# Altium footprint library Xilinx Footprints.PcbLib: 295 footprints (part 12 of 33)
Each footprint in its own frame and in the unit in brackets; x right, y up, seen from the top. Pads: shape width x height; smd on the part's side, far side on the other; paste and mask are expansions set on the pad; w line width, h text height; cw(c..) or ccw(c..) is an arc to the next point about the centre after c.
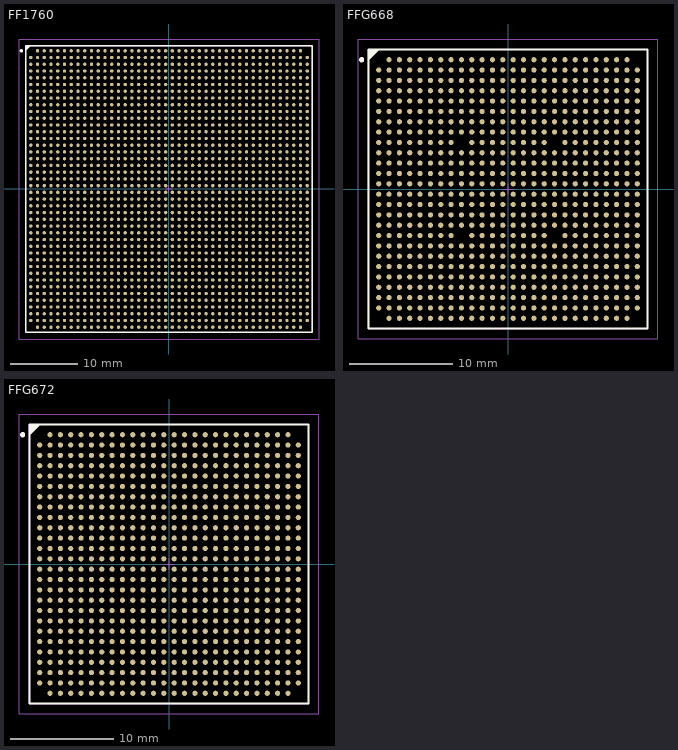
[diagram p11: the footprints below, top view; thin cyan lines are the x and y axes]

## FF1760 [mm] "1760-Ball Flip Chip Fine Pitch Ball Grid Array (FF1760)"
height 3.5
pads (1760):
  round 0.5 smd: A2(-19.5,20.5) A3(-18.5,20.5) A4(-17.5,20.5) A5(-16.5,20.5) A6(-15.5,20.5) A7(-14.5,20.5) A8(-13.5,20.5) A9(-12.5,20.5) A10(-11.5,20.5) A11(-10.5,20.5) A12(-9.5,20.5) A13(-8.5,20.5) A14(-7.5,20.5) A15(-6.5,20.5) A16(-5.5,20.5) A17(-4.5,20.5) A18(-3.5,20.5) A19(-2.5,20.5) A20(-1.5,20.5) A21(-0.5,20.5) A22(0.5,20.5) A23(1.5,20.5) A24(2.5,20.5) A25(3.5,20.5) A26(4.5,20.5) A27(5.5,20.5) A28(6.5,20.5) A29(7.5,20.5) A30(8.5,20.5) A31(9.5,20.5) A32(10.5,20.5) A33(11.5,20.5) A34(12.5,20.5) A35(13.5,20.5) A36(14.5,20.5) A37(15.5,20.5) A38(16.5,20.5) A39(17.5,20.5) A40(18.5,20.5) A41(19.5,20.5) AA1(-20.5,0.5) AA2(-19.5,0.5) AA3(-18.5,0.5) AA4(-17.5,0.5) AA5(-16.5,0.5) AA6(-15.5,0.5) AA7(-14.5,0.5) AA8(-13.5,0.5) AA9(-12.5,0.5) AA10(-11.5,0.5) AA11(-10.5,0.5) AA12(-9.5,0.5) AA13(-8.5,0.5) AA14(-7.5,0.5) AA15(-6.5,0.5) AA16(-5.5,0.5) AA17(-4.5,0.5) AA18(-3.5,0.5) AA19(-2.5,0.5) AA20(-1.5,0.5) AA21(-0.5,0.5) AA22(0.5,0.5) AA23(1.5,0.5) AA24(2.5,0.5) AA25(3.5,0.5) AA26(4.5,0.5) AA27(5.5,0.5) AA28(6.5,0.5) AA29(7.5,0.5) AA30(8.5,0.5) AA31(9.5,0.5) AA32(10.5,0.5) AA33(11.5,0.5) AA34(12.5,0.5) AA35(13.5,0.5) AA36(14.5,0.5) AA37(15.5,0.5) AA38(16.5,0.5) AA39(17.5,0.5) AA40(18.5,0.5) AA41(19.5,0.5) AA42(20.5,0.5) AB1(-20.5,-0.5) AB2(-19.5,-0.5) AB3(-18.5,-0.5) AB4(-17.5,-0.5) AB5(-16.5,-0.5) AB6(-15.5,-0.5) AB7(-14.5,-0.5) AB8(-13.5,-0.5) AB9(-12.5,-0.5) AB10(-11.5,-0.5) AB11(-10.5,-0.5) AB12(-9.5,-0.5) AB13(-8.5,-0.5) AB14(-7.5,-0.5) AB15(-6.5,-0.5) AB16(-5.5,-0.5) AB17(-4.5,-0.5) AB18(-3.5,-0.5) AB19(-2.5,-0.5) AB20(-1.5,-0.5) AB21(-0.5,-0.5) AB22(0.5,-0.5) AB23(1.5,-0.5) AB24(2.5,-0.5) AB25(3.5,-0.5) AB26(4.5,-0.5) AB27(5.5,-0.5) AB28(6.5,-0.5) AB29(7.5,-0.5) AB30(8.5,-0.5) AB31(9.5,-0.5) AB32(10.5,-0.5) AB33(11.5,-0.5) AB34(12.5,-0.5) AB35(13.5,-0.5) AB36(14.5,-0.5) AB37(15.5,-0.5) AB38(16.5,-0.5) AB39(17.5,-0.5) AB40(18.5,-0.5) AB41(19.5,-0.5) AB42(20.5,-0.5) AC1(-20.5,-1.5) AC2(-19.5,-1.5) AC3(-18.5,-1.5) AC4(-17.5,-1.5) AC5(-16.5,-1.5) AC6(-15.5,-1.5) AC7(-14.5,-1.5) AC8(-13.5,-1.5) AC9(-12.5,-1.5) AC10(-11.5,-1.5) AC11(-10.5,-1.5) AC12(-9.5,-1.5) AC13(-8.5,-1.5) AC14(-7.5,-1.5) AC15(-6.5,-1.5) AC16(-5.5,-1.5) AC17(-4.5,-1.5) AC18(-3.5,-1.5) AC19(-2.5,-1.5) AC20(-1.5,-1.5) AC21(-0.5,-1.5) AC22(0.5,-1.5) AC23(1.5,-1.5) AC24(2.5,-1.5) AC25(3.5,-1.5) AC26(4.5,-1.5) AC27(5.5,-1.5) AC28(6.5,-1.5) AC29(7.5,-1.5) AC30(8.5,-1.5) AC31(9.5,-1.5) AC32(10.5,-1.5) AC33(11.5,-1.5) AC34(12.5,-1.5) AC35(13.5,-1.5) AC36(14.5,-1.5) AC37(15.5,-1.5) AC38(16.5,-1.5) AC39(17.5,-1.5) AC40(18.5,-1.5) AC41(19.5,-1.5) AC42(20.5,-1.5) AD1(-20.5,-2.5) AD2(-19.5,-2.5) AD3(-18.5,-2.5) AD4(-17.5,-2.5) AD5(-16.5,-2.5) AD6(-15.5,-2.5) AD7(-14.5,-2.5) AD8(-13.5,-2.5) AD9(-12.5,-2.5) AD10(-11.5,-2.5) AD11(-10.5,-2.5) AD12(-9.5,-2.5) AD13(-8.5,-2.5) AD14(-7.5,-2.5) AD15(-6.5,-2.5) AD16(-5.5,-2.5) AD17(-4.5,-2.5) AD18(-3.5,-2.5) AD19(-2.5,-2.5) AD20(-1.5,-2.5) AD21(-0.5,-2.5) AD22(0.5,-2.5) AD23(1.5,-2.5) AD24(2.5,-2.5) AD25(3.5,-2.5) AD26(4.5,-2.5) AD27(5.5,-2.5) AD28(6.5,-2.5) AD29(7.5,-2.5) AD30(8.5,-2.5) AD31(9.5,-2.5) AD32(10.5,-2.5) AD33(11.5,-2.5) AD34(12.5,-2.5) AD35(13.5,-2.5) AD36(14.5,-2.5) AD37(15.5,-2.5) AD38(16.5,-2.5) AD39(17.5,-2.5) AD40(18.5,-2.5) AD41(19.5,-2.5) AD42(20.5,-2.5) AE1(-20.5,-3.5) AE2(-19.5,-3.5) AE3(-18.5,-3.5) AE4(-17.5,-3.5) AE5(-16.5,-3.5) AE6(-15.5,-3.5) AE7(-14.5,-3.5) AE8(-13.5,-3.5) AE9(-12.5,-3.5) AE10(-11.5,-3.5) AE11(-10.5,-3.5) AE12(-9.5,-3.5) AE13(-8.5,-3.5) AE14(-7.5,-3.5) AE15(-6.5,-3.5) AE16(-5.5,-3.5) AE17(-4.5,-3.5) AE18(-3.5,-3.5) AE19(-2.5,-3.5) AE20(-1.5,-3.5) AE21(-0.5,-3.5) AE22(0.5,-3.5) AE23(1.5,-3.5) AE24(2.5,-3.5) AE25(3.5,-3.5) AE26(4.5,-3.5) AE27(5.5,-3.5) AE28(6.5,-3.5) AE29(7.5,-3.5) AE30(8.5,-3.5) AE31(9.5,-3.5) AE32(10.5,-3.5) AE33(11.5,-3.5) AE34(12.5,-3.5) AE35(13.5,-3.5) AE36(14.5,-3.5) AE37(15.5,-3.5) AE38(16.5,-3.5) AE39(17.5,-3.5) AE40(18.5,-3.5) AE41(19.5,-3.5) AE42(20.5,-3.5) AF1(-20.5,-4.5) AF2(-19.5,-4.5) AF3(-18.5,-4.5) AF4(-17.5,-4.5) AF5(-16.5,-4.5) AF6(-15.5,-4.5) AF7(-14.5,-4.5) AF8(-13.5,-4.5) AF9(-12.5,-4.5) AF10(-11.5,-4.5) AF11(-10.5,-4.5) AF12(-9.5,-4.5) AF13(-8.5,-4.5) AF14(-7.5,-4.5) AF15(-6.5,-4.5) AF16(-5.5,-4.5) AF17(-4.5,-4.5) AF18(-3.5,-4.5) AF19(-2.5,-4.5) AF20(-1.5,-4.5) AF21(-0.5,-4.5) AF22(0.5,-4.5) AF23(1.5,-4.5) AF24(2.5,-4.5) AF25(3.5,-4.5) AF26(4.5,-4.5) AF27(5.5,-4.5) AF28(6.5,-4.5) AF29(7.5,-4.5) AF30(8.5,-4.5) AF31(9.5,-4.5) AF32(10.5,-4.5) AF33(11.5,-4.5) AF34(12.5,-4.5) AF35(13.5,-4.5) AF36(14.5,-4.5) AF37(15.5,-4.5) AF38(16.5,-4.5) AF39(17.5,-4.5) AF40(18.5,-4.5) AF41(19.5,-4.5) AF42(20.5,-4.5) AG1(-20.5,-5.5) AG2(-19.5,-5.5) AG3(-18.5,-5.5) AG4(-17.5,-5.5) AG5(-16.5,-5.5) AG6(-15.5,-5.5) AG7(-14.5,-5.5) AG8(-13.5,-5.5) AG9(-12.5,-5.5) AG10(-11.5,-5.5) AG11(-10.5,-5.5) AG12(-9.5,-5.5) AG13(-8.5,-5.5) AG14(-7.5,-5.5) AG15(-6.5,-5.5) AG16(-5.5,-5.5) AG17(-4.5,-5.5) AG18(-3.5,-5.5) AG19(-2.5,-5.5) AG20(-1.5,-5.5) AG21(-0.5,-5.5) AG22(0.5,-5.5) AG23(1.5,-5.5) AG24(2.5,-5.5) AG25(3.5,-5.5) AG26(4.5,-5.5) AG27(5.5,-5.5) AG28(6.5,-5.5) AG29(7.5,-5.5) AG30(8.5,-5.5) AG31(9.5,-5.5) AG32(10.5,-5.5) AG33(11.5,-5.5) AG34(12.5,-5.5) AG35(13.5,-5.5) AG36(14.5,-5.5) AG37(15.5,-5.5) AG38(16.5,-5.5) AG39(17.5,-5.5) AG40(18.5,-5.5) AG41(19.5,-5.5) AG42(20.5,-5.5) AH1(-20.5,-6.5) AH2(-19.5,-6.5) AH3(-18.5,-6.5) AH4(-17.5,-6.5) AH5(-16.5,-6.5) AH6(-15.5,-6.5) AH7(-14.5,-6.5) AH8(-13.5,-6.5) AH9(-12.5,-6.5) AH10(-11.5,-6.5) AH11(-10.5,-6.5) AH12(-9.5,-6.5) AH13(-8.5,-6.5) AH14(-7.5,-6.5) AH15(-6.5,-6.5) AH16(-5.5,-6.5) AH17(-4.5,-6.5) AH18(-3.5,-6.5) AH19(-2.5,-6.5) AH20(-1.5,-6.5) AH21(-0.5,-6.5) AH22(0.5,-6.5) AH23(1.5,-6.5) AH24(2.5,-6.5) AH25(3.5,-6.5) AH26(4.5,-6.5) AH27(5.5,-6.5) AH28(6.5,-6.5) AH29(7.5,-6.5) AH30(8.5,-6.5) AH31(9.5,-6.5) AH32(10.5,-6.5) AH33(11.5,-6.5) AH34(12.5,-6.5) AH35(13.5,-6.5) AH36(14.5,-6.5) AH37(15.5,-6.5) AH38(16.5,-6.5) AH39(17.5,-6.5) AH40(18.5,-6.5) AH41(19.5,-6.5) AH42(20.5,-6.5) AJ1(-20.5,-7.5) AJ2(-19.5,-7.5) AJ3(-18.5,-7.5) AJ4(-17.5,-7.5) AJ5(-16.5,-7.5) AJ6(-15.5,-7.5) AJ7(-14.5,-7.5) AJ8(-13.5,-7.5) AJ9(-12.5,-7.5) AJ10(-11.5,-7.5) AJ11(-10.5,-7.5) AJ12(-9.5,-7.5) AJ13(-8.5,-7.5) AJ14(-7.5,-7.5) AJ15(-6.5,-7.5) AJ16(-5.5,-7.5) AJ17(-4.5,-7.5) AJ18(-3.5,-7.5) AJ19(-2.5,-7.5) AJ20(-1.5,-7.5) AJ21(-0.5,-7.5) AJ22(0.5,-7.5) AJ23(1.5,-7.5) AJ24(2.5,-7.5) AJ25(3.5,-7.5) AJ26(4.5,-7.5) AJ27(5.5,-7.5) AJ28(6.5,-7.5) AJ29(7.5,-7.5) AJ30(8.5,-7.5) AJ31(9.5,-7.5) AJ32(10.5,-7.5) AJ33(11.5,-7.5) AJ34(12.5,-7.5) AJ35(13.5,-7.5) AJ36(14.5,-7.5) AJ37(15.5,-7.5) AJ38(16.5,-7.5) AJ39(17.5,-7.5) AJ40(18.5,-7.5) AJ41(19.5,-7.5) AJ42(20.5,-7.5) AK1(-20.5,-8.5) AK2(-19.5,-8.5) AK3(-18.5,-8.5) AK4(-17.5,-8.5) AK5(-16.5,-8.5) AK6(-15.5,-8.5) AK7(-14.5,-8.5) AK8(-13.5,-8.5) AK9(-12.5,-8.5) AK10(-11.5,-8.5) AK11(-10.5,-8.5) AK12(-9.5,-8.5) AK13(-8.5,-8.5) AK14(-7.5,-8.5) AK15(-6.5,-8.5) AK16(-5.5,-8.5) AK17(-4.5,-8.5) AK18(-3.5,-8.5) AK19(-2.5,-8.5) AK20(-1.5,-8.5) AK21(-0.5,-8.5) AK22(0.5,-8.5) AK23(1.5,-8.5) AK24(2.5,-8.5) AK25(3.5,-8.5) AK26(4.5,-8.5) AK27(5.5,-8.5) AK28(6.5,-8.5) AK29(7.5,-8.5) AK30(8.5,-8.5) AK31(9.5,-8.5) AK32(10.5,-8.5) AK33(11.5,-8.5) AK34(12.5,-8.5) AK35(13.5,-8.5) AK36(14.5,-8.5) AK37(15.5,-8.5) AK38(16.5,-8.5) AK39(17.5,-8.5) AK40(18.5,-8.5) AK41(19.5,-8.5) AK42(20.5,-8.5) AL1(-20.5,-9.5) AL2(-19.5,-9.5) AL3(-18.5,-9.5) AL4(-17.5,-9.5) AL5(-16.5,-9.5) AL6(-15.5,-9.5) AL7(-14.5,-9.5) AL8(-13.5,-9.5) AL9(-12.5,-9.5) AL10(-11.5,-9.5) AL11(-10.5,-9.5) AL12(-9.5,-9.5) AL13(-8.5,-9.5) AL14(-7.5,-9.5) AL15(-6.5,-9.5) AL16(-5.5,-9.5) AL17(-4.5,-9.5) AL18(-3.5,-9.5) AL19(-2.5,-9.5) AL20(-1.5,-9.5) AL21(-0.5,-9.5) AL22(0.5,-9.5) AL23(1.5,-9.5) AL24(2.5,-9.5) AL25(3.5,-9.5) AL26(4.5,-9.5) AL27(5.5,-9.5) AL28(6.5,-9.5) AL29(7.5,-9.5) AL30(8.5,-9.5) AL31(9.5,-9.5) AL32(10.5,-9.5) AL33(11.5,-9.5) AL34(12.5,-9.5) AL35(13.5,-9.5) AL36(14.5,-9.5) AL37(15.5,-9.5) AL38(16.5,-9.5) AL39(17.5,-9.5) AL40(18.5,-9.5) AL41(19.5,-9.5) AL42(20.5,-9.5) AM1(-20.5,-10.5) AM2(-19.5,-10.5) AM3(-18.5,-10.5) AM4(-17.5,-10.5) AM5(-16.5,-10.5) AM6(-15.5,-10.5) AM7(-14.5,-10.5) AM8(-13.5,-10.5) AM9(-12.5,-10.5) AM10(-11.5,-10.5) AM11(-10.5,-10.5) AM12(-9.5,-10.5) AM13(-8.5,-10.5) AM14(-7.5,-10.5) AM15(-6.5,-10.5) AM16(-5.5,-10.5) AM17(-4.5,-10.5) AM18(-3.5,-10.5) AM19(-2.5,-10.5) AM20(-1.5,-10.5) AM21(-0.5,-10.5) AM22(0.5,-10.5) AM23(1.5,-10.5) AM24(2.5,-10.5) AM25(3.5,-10.5) AM26(4.5,-10.5) AM27(5.5,-10.5) AM28(6.5,-10.5) AM29(7.5,-10.5) AM30(8.5,-10.5) AM31(9.5,-10.5) AM32(10.5,-10.5) AM33(11.5,-10.5) AM34(12.5,-10.5) AM35(13.5,-10.5) AM36(14.5,-10.5) AM37(15.5,-10.5) AM38(16.5,-10.5) AM39(17.5,-10.5) AM40(18.5,-10.5) AM41(19.5,-10.5) AM42(20.5,-10.5) AN1(-20.5,-11.5) AN2(-19.5,-11.5) AN3(-18.5,-11.5) AN4(-17.5,-11.5) AN5(-16.5,-11.5) AN6(-15.5,-11.5) AN7(-14.5,-11.5) AN8(-13.5,-11.5) AN9(-12.5,-11.5) AN10(-11.5,-11.5) AN11(-10.5,-11.5) AN12(-9.5,-11.5) AN13(-8.5,-11.5) AN14(-7.5,-11.5) AN15(-6.5,-11.5) AN16(-5.5,-11.5) AN17(-4.5,-11.5) AN18(-3.5,-11.5) AN19(-2.5,-11.5) AN20(-1.5,-11.5) AN21(-0.5,-11.5) AN22(0.5,-11.5) AN23(1.5,-11.5) AN24(2.5,-11.5) AN25(3.5,-11.5) AN26(4.5,-11.5) AN27(5.5,-11.5) AN28(6.5,-11.5) AN29(7.5,-11.5) AN30(8.5,-11.5) AN31(9.5,-11.5) AN32(10.5,-11.5) AN33(11.5,-11.5) AN34(12.5,-11.5) AN35(13.5,-11.5) AN36(14.5,-11.5) AN37(15.5,-11.5) AN38(16.5,-11.5) AN39(17.5,-11.5) AN40(18.5,-11.5) AN41(19.5,-11.5) AN42(20.5,-11.5) AP1(-20.5,-12.5) AP2(-19.5,-12.5) AP3(-18.5,-12.5) AP4(-17.5,-12.5) AP5(-16.5,-12.5) AP6(-15.5,-12.5) AP7(-14.5,-12.5) AP8(-13.5,-12.5) AP9(-12.5,-12.5) AP10(-11.5,-12.5) AP11(-10.5,-12.5) AP12(-9.5,-12.5) AP13(-8.5,-12.5) AP14(-7.5,-12.5) AP15(-6.5,-12.5) AP16(-5.5,-12.5) AP17(-4.5,-12.5) AP18(-3.5,-12.5) AP19(-2.5,-12.5) AP20(-1.5,-12.5) AP21(-0.5,-12.5) AP22(0.5,-12.5) AP23(1.5,-12.5) AP24(2.5,-12.5) AP25(3.5,-12.5) AP26(4.5,-12.5) AP27(5.5,-12.5) AP28(6.5,-12.5) AP29(7.5,-12.5) AP30(8.5,-12.5) AP31(9.5,-12.5) AP32(10.5,-12.5) AP33(11.5,-12.5) AP34(12.5,-12.5) AP35(13.5,-12.5) AP36(14.5,-12.5) AP37(15.5,-12.5) AP38(16.5,-12.5) AP39(17.5,-12.5) AP40(18.5,-12.5) AP41(19.5,-12.5) AP42(20.5,-12.5) AR1(-20.5,-13.5) AR2(-19.5,-13.5) AR3(-18.5,-13.5) AR4(-17.5,-13.5) AR5(-16.5,-13.5) AR6(-15.5,-13.5) AR7(-14.5,-13.5) AR8(-13.5,-13.5) AR9(-12.5,-13.5) AR10(-11.5,-13.5) AR11(-10.5,-13.5) AR12(-9.5,-13.5) AR13(-8.5,-13.5) AR14(-7.5,-13.5) AR15(-6.5,-13.5) AR16(-5.5,-13.5) AR17(-4.5,-13.5) AR18(-3.5,-13.5) AR19(-2.5,-13.5) AR20(-1.5,-13.5) AR21(-0.5,-13.5) AR22(0.5,-13.5) AR23(1.5,-13.5) AR24(2.5,-13.5) AR25(3.5,-13.5) AR26(4.5,-13.5) AR27(5.5,-13.5) AR28(6.5,-13.5) AR29(7.5,-13.5) AR30(8.5,-13.5) AR31(9.5,-13.5) AR32(10.5,-13.5) AR33(11.5,-13.5) AR34(12.5,-13.5) AR35(13.5,-13.5) AR36(14.5,-13.5) AR37(15.5,-13.5) AR38(16.5,-13.5) AR39(17.5,-13.5) AR40(18.5,-13.5) AR41(19.5,-13.5) AR42(20.5,-13.5) AT1(-20.5,-14.5) AT2(-19.5,-14.5) AT3(-18.5,-14.5) AT4(-17.5,-14.5) AT5(-16.5,-14.5) AT6(-15.5,-14.5) AT7(-14.5,-14.5) AT8(-13.5,-14.5) AT9(-12.5,-14.5) AT10(-11.5,-14.5) AT11(-10.5,-14.5) AT12(-9.5,-14.5) AT13(-8.5,-14.5) AT14(-7.5,-14.5) AT15(-6.5,-14.5) AT16(-5.5,-14.5) AT17(-4.5,-14.5) AT18(-3.5,-14.5) AT19(-2.5,-14.5) AT20(-1.5,-14.5) AT21(-0.5,-14.5) AT22(0.5,-14.5) AT23(1.5,-14.5) AT24(2.5,-14.5) AT25(3.5,-14.5) AT26(4.5,-14.5) AT27(5.5,-14.5) AT28(6.5,-14.5) AT29(7.5,-14.5) AT30(8.5,-14.5) AT31(9.5,-14.5) AT32(10.5,-14.5) AT33(11.5,-14.5) AT34(12.5,-14.5) AT35(13.5,-14.5) AT36(14.5,-14.5) AT37(15.5,-14.5) AT38(16.5,-14.5) AT39(17.5,-14.5) AT40(18.5,-14.5) AT41(19.5,-14.5) AT42(20.5,-14.5) AU1(-20.5,-15.5) AU2(-19.5,-15.5) AU3(-18.5,-15.5) AU4(-17.5,-15.5) AU5(-16.5,-15.5) AU6(-15.5,-15.5) AU7(-14.5,-15.5) AU8(-13.5,-15.5) AU9(-12.5,-15.5) AU10(-11.5,-15.5) AU11(-10.5,-15.5) AU12(-9.5,-15.5) AU13(-8.5,-15.5) AU14(-7.5,-15.5) AU15(-6.5,-15.5) AU16(-5.5,-15.5) AU17(-4.5,-15.5) AU18(-3.5,-15.5) AU19(-2.5,-15.5) AU20(-1.5,-15.5) AU21(-0.5,-15.5) AU22(0.5,-15.5) AU23(1.5,-15.5) AU24(2.5,-15.5) AU25(3.5,-15.5) AU26(4.5,-15.5) AU27(5.5,-15.5) AU28(6.5,-15.5) AU29(7.5,-15.5) AU30(8.5,-15.5) AU31(9.5,-15.5) AU32(10.5,-15.5) AU33(11.5,-15.5) AU34(12.5,-15.5) AU35(13.5,-15.5) AU36(14.5,-15.5) AU37(15.5,-15.5) AU38(16.5,-15.5) AU39(17.5,-15.5) AU40(18.5,-15.5) AU41(19.5,-15.5) AU42(20.5,-15.5) AV1(-20.5,-16.5) AV2(-19.5,-16.5) AV3(-18.5,-16.5) AV4(-17.5,-16.5) AV5(-16.5,-16.5) AV6(-15.5,-16.5) AV7(-14.5,-16.5) AV8(-13.5,-16.5) AV9(-12.5,-16.5) AV10(-11.5,-16.5) AV11(-10.5,-16.5) AV12(-9.5,-16.5) AV13(-8.5,-16.5) AV14(-7.5,-16.5) AV15(-6.5,-16.5) AV16(-5.5,-16.5) AV17(-4.5,-16.5) AV18(-3.5,-16.5) AV19(-2.5,-16.5) AV20(-1.5,-16.5) AV21(-0.5,-16.5) AV22(0.5,-16.5) AV23(1.5,-16.5) AV24(2.5,-16.5) AV25(3.5,-16.5) AV26(4.5,-16.5) AV27(5.5,-16.5) AV28(6.5,-16.5) AV29(7.5,-16.5) AV30(8.5,-16.5) AV31(9.5,-16.5) AV32(10.5,-16.5) AV33(11.5,-16.5) AV34(12.5,-16.5) AV35(13.5,-16.5) AV36(14.5,-16.5) AV37(15.5,-16.5) AV38(16.5,-16.5) AV39(17.5,-16.5) AV40(18.5,-16.5) AV41(19.5,-16.5) AV42(20.5,-16.5) AW1(-20.5,-17.5) AW2(-19.5,-17.5) AW3(-18.5,-17.5) AW4(-17.5,-17.5) AW5(-16.5,-17.5) AW6(-15.5,-17.5) AW7(-14.5,-17.5) AW8(-13.5,-17.5) AW9(-12.5,-17.5) AW10(-11.5,-17.5) AW11(-10.5,-17.5) AW12(-9.5,-17.5) AW13(-8.5,-17.5) AW14(-7.5,-17.5) AW15(-6.5,-17.5) AW16(-5.5,-17.5) AW17(-4.5,-17.5) AW18(-3.5,-17.5) AW19(-2.5,-17.5) AW20(-1.5,-17.5) AW21(-0.5,-17.5) AW22(0.5,-17.5) AW23(1.5,-17.5) AW24(2.5,-17.5) AW25(3.5,-17.5) AW26(4.5,-17.5) AW27(5.5,-17.5) AW28(6.5,-17.5) AW29(7.5,-17.5) AW30(8.5,-17.5) AW31(9.5,-17.5) AW32(10.5,-17.5) AW33(11.5,-17.5) AW34(12.5,-17.5) AW35(13.5,-17.5) AW36(14.5,-17.5) AW37(15.5,-17.5) AW38(16.5,-17.5) AW39(17.5,-17.5) AW40(18.5,-17.5) AW41(19.5,-17.5) AW42(20.5,-17.5) AY1(-20.5,-18.5) AY2(-19.5,-18.5) AY3(-18.5,-18.5) AY4(-17.5,-18.5) AY5(-16.5,-18.5) AY6(-15.5,-18.5) AY7(-14.5,-18.5) AY8(-13.5,-18.5) AY9(-12.5,-18.5) AY10(-11.5,-18.5) AY11(-10.5,-18.5) AY12(-9.5,-18.5) AY13(-8.5,-18.5) AY14(-7.5,-18.5) AY15(-6.5,-18.5) AY16(-5.5,-18.5) AY17(-4.5,-18.5) AY18(-3.5,-18.5) AY19(-2.5,-18.5) AY20(-1.5,-18.5) AY21(-0.5,-18.5) AY22(0.5,-18.5) AY23(1.5,-18.5) AY24(2.5,-18.5) AY25(3.5,-18.5) AY26(4.5,-18.5) AY27(5.5,-18.5) AY28(6.5,-18.5) AY29(7.5,-18.5) AY30(8.5,-18.5) AY31(9.5,-18.5) AY32(10.5,-18.5) AY33(11.5,-18.5) AY34(12.5,-18.5) AY35(13.5,-18.5) AY36(14.5,-18.5) AY37(15.5,-18.5) AY38(16.5,-18.5) AY39(17.5,-18.5) AY40(18.5,-18.5) AY41(19.5,-18.5) AY42(20.5,-18.5) B1(-20.5,19.5) B2(-19.5,19.5) B3(-18.5,19.5) B4(-17.5,19.5) B5(-16.5,19.5) B6(-15.5,19.5) B7(-14.5,19.5) B8(-13.5,19.5) B9(-12.5,19.5) B10(-11.5,19.5) B11(-10.5,19.5) B12(-9.5,19.5) B13(-8.5,19.5) B14(-7.5,19.5) B15(-6.5,19.5) B16(-5.5,19.5) B17(-4.5,19.5) B18(-3.5,19.5) B19(-2.5,19.5) B20(-1.5,19.5) B21(-0.5,19.5) B22(0.5,19.5) B23(1.5,19.5) B24(2.5,19.5) B25(3.5,19.5) B26(4.5,19.5) B27(5.5,19.5) B28(6.5,19.5) B29(7.5,19.5) B30(8.5,19.5) B31(9.5,19.5) B32(10.5,19.5) B33(11.5,19.5) B34(12.5,19.5) B35(13.5,19.5) B36(14.5,19.5) B37(15.5,19.5) B38(16.5,19.5) B39(17.5,19.5) B40(18.5,19.5) B41(19.5,19.5) B42(20.5,19.5) BA1(-20.5,-19.5) BA2(-19.5,-19.5) BA3(-18.5,-19.5) BA4(-17.5,-19.5) BA5(-16.5,-19.5) BA6(-15.5,-19.5) BA7(-14.5,-19.5) BA8(-13.5,-19.5) BA9(-12.5,-19.5) BA10(-11.5,-19.5) BA11(-10.5,-19.5) BA12(-9.5,-19.5) BA13(-8.5,-19.5) BA14(-7.5,-19.5) BA15(-6.5,-19.5) BA16(-5.5,-19.5) BA17(-4.5,-19.5) BA18(-3.5,-19.5) BA19(-2.5,-19.5) BA20(-1.5,-19.5) BA21(-0.5,-19.5) BA22(0.5,-19.5) BA23(1.5,-19.5) BA24(2.5,-19.5) BA25(3.5,-19.5) BA26(4.5,-19.5) BA27(5.5,-19.5) BA28(6.5,-19.5) BA29(7.5,-19.5) BA30(8.5,-19.5) BA31(9.5,-19.5) BA32(10.5,-19.5) BA33(11.5,-19.5) BA34(12.5,-19.5) BA35(13.5,-19.5) BA36(14.5,-19.5) BA37(15.5,-19.5) BA38(16.5,-19.5) BA39(17.5,-19.5) BA40(18.5,-19.5) BA41(19.5,-19.5) BA42(20.5,-19.5) BB2(-19.5,-20.5) BB3(-18.5,-20.5) BB4(-17.5,-20.5) BB5(-16.5,-20.5) BB6(-15.5,-20.5) BB7(-14.5,-20.5) BB8(-13.5,-20.5) BB9(-12.5,-20.5) BB10(-11.5,-20.5) BB11(-10.5,-20.5) BB12(-9.5,-20.5) BB13(-8.5,-20.5) BB14(-7.5,-20.5) BB15(-6.5,-20.5) BB16(-5.5,-20.5) BB17(-4.5,-20.5) BB18(-3.5,-20.5) BB19(-2.5,-20.5) BB20(-1.5,-20.5) BB21(-0.5,-20.5) BB22(0.5,-20.5) BB23(1.5,-20.5) BB24(2.5,-20.5) BB25(3.5,-20.5) BB26(4.5,-20.5) BB27(5.5,-20.5) BB28(6.5,-20.5) BB29(7.5,-20.5) BB30(8.5,-20.5) BB31(9.5,-20.5) BB32(10.5,-20.5) BB33(11.5,-20.5) BB34(12.5,-20.5) BB35(13.5,-20.5) BB36(14.5,-20.5) BB37(15.5,-20.5) BB38(16.5,-20.5) BB39(17.5,-20.5) BB40(18.5,-20.5) BB41(19.5,-20.5) C1(-20.5,18.5) C2(-19.5,18.5) C3(-18.5,18.5) C4(-17.5,18.5) C5(-16.5,18.5) C6(-15.5,18.5) C7(-14.5,18.5) C8(-13.5,18.5) C9(-12.5,18.5) C10(-11.5,18.5) C11(-10.5,18.5) C12(-9.5,18.5) C13(-8.5,18.5) C14(-7.5,18.5) C15(-6.5,18.5) C16(-5.5,18.5) C17(-4.5,18.5) C18(-3.5,18.5) C19(-2.5,18.5) C20(-1.5,18.5) C21(-0.5,18.5) C22(0.5,18.5) C23(1.5,18.5) C24(2.5,18.5) C25(3.5,18.5) C26(4.5,18.5) C27(5.5,18.5) C28(6.5,18.5) C29(7.5,18.5) C30(8.5,18.5) C31(9.5,18.5) C32(10.5,18.5) C33(11.5,18.5) C34(12.5,18.5) C35(13.5,18.5) C36(14.5,18.5) C37(15.5,18.5) C38(16.5,18.5) C39(17.5,18.5) C40(18.5,18.5) C41(19.5,18.5) C42(20.5,18.5) D1(-20.5,17.5) D2(-19.5,17.5) D3(-18.5,17.5) D4(-17.5,17.5) D5(-16.5,17.5) D6(-15.5,17.5) D7(-14.5,17.5) D8(-13.5,17.5) D9(-12.5,17.5) D10(-11.5,17.5) D11(-10.5,17.5) D12(-9.5,17.5) D13(-8.5,17.5) D14(-7.5,17.5) D15(-6.5,17.5) D16(-5.5,17.5) D17(-4.5,17.5) D18(-3.5,17.5) D19(-2.5,17.5) D20(-1.5,17.5) D21(-0.5,17.5) D22(0.5,17.5) D23(1.5,17.5) D24(2.5,17.5) D25(3.5,17.5) D26(4.5,17.5) D27(5.5,17.5) D28(6.5,17.5) D29(7.5,17.5) D30(8.5,17.5) D31(9.5,17.5) D32(10.5,17.5) D33(11.5,17.5) D34(12.5,17.5) D35(13.5,17.5) D36(14.5,17.5) D37(15.5,17.5) D38(16.5,17.5) D39(17.5,17.5) D40(18.5,17.5) D41(19.5,17.5) D42(20.5,17.5) E1(-20.5,16.5) E2(-19.5,16.5) E3(-18.5,16.5) E4(-17.5,16.5) E5(-16.5,16.5) E6(-15.5,16.5) E7(-14.5,16.5) E8(-13.5,16.5) E9(-12.5,16.5) E10(-11.5,16.5) E11(-10.5,16.5) E12(-9.5,16.5) E13(-8.5,16.5) E14(-7.5,16.5) E15(-6.5,16.5) E16(-5.5,16.5) E17(-4.5,16.5) E18(-3.5,16.5) E19(-2.5,16.5) E20(-1.5,16.5) E21(-0.5,16.5) E22(0.5,16.5) E23(1.5,16.5) E24(2.5,16.5) E25(3.5,16.5) E26(4.5,16.5) E27(5.5,16.5) E28(6.5,16.5) E29(7.5,16.5) E30(8.5,16.5) E31(9.5,16.5) E32(10.5,16.5) E33(11.5,16.5) E34(12.5,16.5) E35(13.5,16.5) E36(14.5,16.5) E37(15.5,16.5) E38(16.5,16.5) E39(17.5,16.5) E40(18.5,16.5) E41(19.5,16.5) E42(20.5,16.5) F1(-20.5,15.5) F2(-19.5,15.5) F3(-18.5,15.5) F4(-17.5,15.5) F5(-16.5,15.5) F6(-15.5,15.5) F7(-14.5,15.5) F8(-13.5,15.5) F9(-12.5,15.5) F10(-11.5,15.5) F11(-10.5,15.5) F12(-9.5,15.5) F13(-8.5,15.5) F14(-7.5,15.5) F15(-6.5,15.5) F16(-5.5,15.5) F17(-4.5,15.5) F18(-3.5,15.5) F19(-2.5,15.5) F20(-1.5,15.5) F21(-0.5,15.5) F22(0.5,15.5) F23(1.5,15.5) F24(2.5,15.5) F25(3.5,15.5) F26(4.5,15.5) F27(5.5,15.5) F28(6.5,15.5) F29(7.5,15.5) F30(8.5,15.5) F31(9.5,15.5) F32(10.5,15.5) F33(11.5,15.5) F34(12.5,15.5) F35(13.5,15.5) F36(14.5,15.5) F37(15.5,15.5) F38(16.5,15.5) F39(17.5,15.5) F40(18.5,15.5) F41(19.5,15.5) F42(20.5,15.5) G1(-20.5,14.5) G2(-19.5,14.5) G3(-18.5,14.5) G4(-17.5,14.5) G5(-16.5,14.5) G6(-15.5,14.5) G7(-14.5,14.5) G8(-13.5,14.5) G9(-12.5,14.5) G10(-11.5,14.5) G11(-10.5,14.5) G12(-9.5,14.5) G13(-8.5,14.5) G14(-7.5,14.5) G15(-6.5,14.5) G16(-5.5,14.5) G17(-4.5,14.5) G18(-3.5,14.5) G19(-2.5,14.5) G20(-1.5,14.5) G21(-0.5,14.5) G22(0.5,14.5) G23(1.5,14.5) G24(2.5,14.5) G25(3.5,14.5) G26(4.5,14.5) G27(5.5,14.5) G28(6.5,14.5) G29(7.5,14.5) G30(8.5,14.5) G31(9.5,14.5) G32(10.5,14.5) G33(11.5,14.5) G34(12.5,14.5) G35(13.5,14.5) G36(14.5,14.5) G37(15.5,14.5) G38(16.5,14.5) G39(17.5,14.5) G40(18.5,14.5) G41(19.5,14.5) G42(20.5,14.5) H1(-20.5,13.5) H2(-19.5,13.5) H3(-18.5,13.5) H4(-17.5,13.5) H5(-16.5,13.5) H6(-15.5,13.5) H7(-14.5,13.5) H8(-13.5,13.5) H9(-12.5,13.5) H10(-11.5,13.5) H11(-10.5,13.5) H12(-9.5,13.5) H13(-8.5,13.5) H14(-7.5,13.5) H15(-6.5,13.5) H16(-5.5,13.5) H17(-4.5,13.5) H18(-3.5,13.5) H19(-2.5,13.5) H20(-1.5,13.5) H21(-0.5,13.5) H22(0.5,13.5) H23(1.5,13.5) H24(2.5,13.5) H25(3.5,13.5) H26(4.5,13.5) H27(5.5,13.5) H28(6.5,13.5) H29(7.5,13.5) H30(8.5,13.5) H31(9.5,13.5) H32(10.5,13.5) H33(11.5,13.5) H34(12.5,13.5) H35(13.5,13.5) H36(14.5,13.5) H37(15.5,13.5) H38(16.5,13.5) H39(17.5,13.5) H40(18.5,13.5) H41(19.5,13.5) H42(20.5,13.5) J1(-20.5,12.5) J2(-19.5,12.5) J3(-18.5,12.5) J4(-17.5,12.5) J5(-16.5,12.5) J6(-15.5,12.5) J7(-14.5,12.5) J8(-13.5,12.5) J9(-12.5,12.5) J10(-11.5,12.5) J11(-10.5,12.5) J12(-9.5,12.5) J13(-8.5,12.5) J14(-7.5,12.5) J15(-6.5,12.5) J16(-5.5,12.5) J17(-4.5,12.5) J18(-3.5,12.5) J19(-2.5,12.5) J20(-1.5,12.5) J21(-0.5,12.5) J22(0.5,12.5) J23(1.5,12.5) J24(2.5,12.5) J25(3.5,12.5) J26(4.5,12.5) J27(5.5,12.5) J28(6.5,12.5) J29(7.5,12.5) J30(8.5,12.5) J31(9.5,12.5) J32(10.5,12.5) J33(11.5,12.5) J34(12.5,12.5) J35(13.5,12.5) J36(14.5,12.5) J37(15.5,12.5) J38(16.5,12.5) J39(17.5,12.5) J40(18.5,12.5) J41(19.5,12.5) J42(20.5,12.5) K1(-20.5,11.5) K2(-19.5,11.5) K3(-18.5,11.5) K4(-17.5,11.5) K5(-16.5,11.5) K6(-15.5,11.5) K7(-14.5,11.5) K8(-13.5,11.5) K9(-12.5,11.5) K10(-11.5,11.5) K11(-10.5,11.5) K12(-9.5,11.5) K13(-8.5,11.5) K14(-7.5,11.5) K15(-6.5,11.5) K16(-5.5,11.5) K17(-4.5,11.5) K18(-3.5,11.5) K19(-2.5,11.5) K20(-1.5,11.5) K21(-0.5,11.5) K22(0.5,11.5) K23(1.5,11.5) K24(2.5,11.5) K25(3.5,11.5) K26(4.5,11.5) K27(5.5,11.5) K28(6.5,11.5) K29(7.5,11.5) K30(8.5,11.5) K31(9.5,11.5) K32(10.5,11.5) K33(11.5,11.5) K34(12.5,11.5) K35(13.5,11.5) K36(14.5,11.5) K37(15.5,11.5) K38(16.5,11.5) K39(17.5,11.5) K40(18.5,11.5) K41(19.5,11.5) K42(20.5,11.5) L1(-20.5,10.5) L2(-19.5,10.5) L3(-18.5,10.5) L4(-17.5,10.5) L5(-16.5,10.5) L6(-15.5,10.5) L7(-14.5,10.5) L8(-13.5,10.5) L9(-12.5,10.5) L10(-11.5,10.5) L11(-10.5,10.5) L12(-9.5,10.5) L13(-8.5,10.5) L14(-7.5,10.5) L15(-6.5,10.5) L16(-5.5,10.5) L17(-4.5,10.5) L18(-3.5,10.5) L19(-2.5,10.5) L20(-1.5,10.5) L21(-0.5,10.5) L22(0.5,10.5) L23(1.5,10.5) L24(2.5,10.5) L25(3.5,10.5) L26(4.5,10.5) L27(5.5,10.5) L28(6.5,10.5) L29(7.5,10.5) L30(8.5,10.5) L31(9.5,10.5) L32(10.5,10.5) L33(11.5,10.5) L34(12.5,10.5) L35(13.5,10.5) L36(14.5,10.5) L37(15.5,10.5) L38(16.5,10.5) L39(17.5,10.5) L40(18.5,10.5) L41(19.5,10.5) L42(20.5,10.5) M1(-20.5,9.5) M2(-19.5,9.5) M3(-18.5,9.5) M4(-17.5,9.5) M5(-16.5,9.5) M6(-15.5,9.5) M7(-14.5,9.5) M8(-13.5,9.5) M9(-12.5,9.5) M10(-11.5,9.5) M11(-10.5,9.5) M12(-9.5,9.5) M13(-8.5,9.5) M14(-7.5,9.5) M15(-6.5,9.5) M16(-5.5,9.5) M17(-4.5,9.5) M18(-3.5,9.5) M19(-2.5,9.5) M20(-1.5,9.5) M21(-0.5,9.5) M22(0.5,9.5) M23(1.5,9.5) M24(2.5,9.5) M25(3.5,9.5) M26(4.5,9.5) M27(5.5,9.5) M28(6.5,9.5) M29(7.5,9.5) M30(8.5,9.5) M31(9.5,9.5) M32(10.5,9.5) M33(11.5,9.5) M34(12.5,9.5) M35(13.5,9.5) M36(14.5,9.5) M37(15.5,9.5) M38(16.5,9.5) M39(17.5,9.5) M40(18.5,9.5) M41(19.5,9.5) M42(20.5,9.5) N1(-20.5,8.5) N2(-19.5,8.5) N3(-18.5,8.5) N4(-17.5,8.5) N5(-16.5,8.5) N6(-15.5,8.5) N7(-14.5,8.5) N8(-13.5,8.5) N9(-12.5,8.5) N10(-11.5,8.5) N11(-10.5,8.5) N12(-9.5,8.5) N13(-8.5,8.5) N14(-7.5,8.5) N15(-6.5,8.5) N16(-5.5,8.5) N17(-4.5,8.5) N18(-3.5,8.5) N19(-2.5,8.5) N20(-1.5,8.5) N21(-0.5,8.5) N22(0.5,8.5) N23(1.5,8.5) N24(2.5,8.5) N25(3.5,8.5) N26(4.5,8.5) N27(5.5,8.5) N28(6.5,8.5) N29(7.5,8.5) N30(8.5,8.5) N31(9.5,8.5) N32(10.5,8.5) N33(11.5,8.5) N34(12.5,8.5) N35(13.5,8.5) N36(14.5,8.5) N37(15.5,8.5) N38(16.5,8.5) N39(17.5,8.5) N40(18.5,8.5) N41(19.5,8.5) N42(20.5,8.5) P1(-20.5,7.5) P2(-19.5,7.5) P3(-18.5,7.5) P4(-17.5,7.5) P5(-16.5,7.5) P6(-15.5,7.5) P7(-14.5,7.5) P8(-13.5,7.5) P9(-12.5,7.5) P10(-11.5,7.5) P11(-10.5,7.5) P12(-9.5,7.5) P13(-8.5,7.5) P14(-7.5,7.5) P15(-6.5,7.5) P16(-5.5,7.5) P17(-4.5,7.5) P18(-3.5,7.5) P19(-2.5,7.5) P20(-1.5,7.5) P21(-0.5,7.5) P22(0.5,7.5) P23(1.5,7.5) P24(2.5,7.5) P25(3.5,7.5) P26(4.5,7.5) P27(5.5,7.5) P28(6.5,7.5) P29(7.5,7.5) P30(8.5,7.5) P31(9.5,7.5) P32(10.5,7.5) P33(11.5,7.5) P34(12.5,7.5) P35(13.5,7.5) P36(14.5,7.5) P37(15.5,7.5) P38(16.5,7.5) P39(17.5,7.5) P40(18.5,7.5) P41(19.5,7.5) P42(20.5,7.5) R1(-20.5,6.5) R2(-19.5,6.5) R3(-18.5,6.5) R4(-17.5,6.5) R5(-16.5,6.5) R6(-15.5,6.5) R7(-14.5,6.5) R8(-13.5,6.5) R9(-12.5,6.5) R10(-11.5,6.5) R11(-10.5,6.5) R12(-9.5,6.5) R13(-8.5,6.5) R14(-7.5,6.5) R15(-6.5,6.5) R16(-5.5,6.5) R17(-4.5,6.5) R18(-3.5,6.5) R19(-2.5,6.5) R20(-1.5,6.5) R21(-0.5,6.5) R22(0.5,6.5) R23(1.5,6.5) R24(2.5,6.5) R25(3.5,6.5) R26(4.5,6.5) R27(5.5,6.5) R28(6.5,6.5) R29(7.5,6.5) R30(8.5,6.5) R31(9.5,6.5) R32(10.5,6.5) R33(11.5,6.5) R34(12.5,6.5) R35(13.5,6.5) R36(14.5,6.5) R37(15.5,6.5) R38(16.5,6.5) R39(17.5,6.5) R40(18.5,6.5) R41(19.5,6.5) R42(20.5,6.5) T1(-20.5,5.5) T2(-19.5,5.5) T3(-18.5,5.5) T4(-17.5,5.5) T5(-16.5,5.5) T6(-15.5,5.5) T7(-14.5,5.5) T8(-13.5,5.5) T9(-12.5,5.5) T10(-11.5,5.5) T11(-10.5,5.5) T12(-9.5,5.5) T13(-8.5,5.5) T14(-7.5,5.5) T15(-6.5,5.5) T16(-5.5,5.5) T17(-4.5,5.5) T18(-3.5,5.5) T19(-2.5,5.5) T20(-1.5,5.5) T21(-0.5,5.5) T22(0.5,5.5) T23(1.5,5.5) T24(2.5,5.5) T25(3.5,5.5) T26(4.5,5.5) T27(5.5,5.5) T28(6.5,5.5) T29(7.5,5.5) T30(8.5,5.5) T31(9.5,5.5) T32(10.5,5.5) T33(11.5,5.5) T34(12.5,5.5) T35(13.5,5.5) T36(14.5,5.5) T37(15.5,5.5) T38(16.5,5.5) T39(17.5,5.5) T40(18.5,5.5) T41(19.5,5.5) T42(20.5,5.5) U1(-20.5,4.5) U2(-19.5,4.5) U3(-18.5,4.5) U4(-17.5,4.5) U5(-16.5,4.5) U6(-15.5,4.5) U7(-14.5,4.5) U8(-13.5,4.5) U9(-12.5,4.5) U10(-11.5,4.5) U11(-10.5,4.5) U12(-9.5,4.5) U13(-8.5,4.5) U14(-7.5,4.5) U15(-6.5,4.5) U16(-5.5,4.5) U17(-4.5,4.5) U18(-3.5,4.5) U19(-2.5,4.5) U20(-1.5,4.5) U21(-0.5,4.5) U22(0.5,4.5) U23(1.5,4.5) U24(2.5,4.5) U25(3.5,4.5) U26(4.5,4.5) U27(5.5,4.5) U28(6.5,4.5) U29(7.5,4.5) U30(8.5,4.5) U31(9.5,4.5) U32(10.5,4.5) U33(11.5,4.5) U34(12.5,4.5) U35(13.5,4.5) U36(14.5,4.5) U37(15.5,4.5) U38(16.5,4.5) U39(17.5,4.5) U40(18.5,4.5) U41(19.5,4.5) U42(20.5,4.5) V1(-20.5,3.5) V2(-19.5,3.5) V3(-18.5,3.5) V4(-17.5,3.5) V5(-16.5,3.5) V6(-15.5,3.5) V7(-14.5,3.5) V8(-13.5,3.5) V9(-12.5,3.5) V10(-11.5,3.5) V11(-10.5,3.5) V12(-9.5,3.5) V13(-8.5,3.5) V14(-7.5,3.5) V15(-6.5,3.5) V16(-5.5,3.5) V17(-4.5,3.5) V18(-3.5,3.5) V19(-2.5,3.5) V20(-1.5,3.5) V21(-0.5,3.5) V22(0.5,3.5) V23(1.5,3.5) V24(2.5,3.5) V25(3.5,3.5) V26(4.5,3.5) V27(5.5,3.5) V28(6.5,3.5) V29(7.5,3.5) V30(8.5,3.5) V31(9.5,3.5) V32(10.5,3.5) V33(11.5,3.5) V34(12.5,3.5) V35(13.5,3.5) V36(14.5,3.5) V37(15.5,3.5) V38(16.5,3.5) V39(17.5,3.5) V40(18.5,3.5) V41(19.5,3.5) V42(20.5,3.5) W1(-20.5,2.5) W2(-19.5,2.5) W3(-18.5,2.5) W4(-17.5,2.5) W5(-16.5,2.5) W6(-15.5,2.5) W7(-14.5,2.5) W8(-13.5,2.5) W9(-12.5,2.5) W10(-11.5,2.5) W11(-10.5,2.5) W12(-9.5,2.5) W13(-8.5,2.5) W14(-7.5,2.5) W15(-6.5,2.5) W16(-5.5,2.5) W17(-4.5,2.5) W18(-3.5,2.5) W19(-2.5,2.5) W20(-1.5,2.5) W21(-0.5,2.5) W22(0.5,2.5) W23(1.5,2.5) W24(2.5,2.5) W25(3.5,2.5) W26(4.5,2.5) W27(5.5,2.5) W28(6.5,2.5) W29(7.5,2.5) W30(8.5,2.5) W31(9.5,2.5) W32(10.5,2.5) W33(11.5,2.5) W34(12.5,2.5) W35(13.5,2.5) W36(14.5,2.5) W37(15.5,2.5) W38(16.5,2.5) W39(17.5,2.5) W40(18.5,2.5) W41(19.5,2.5) W42(20.5,2.5) Y1(-20.5,1.5) Y2(-19.5,1.5) Y3(-18.5,1.5) Y4(-17.5,1.5) Y5(-16.5,1.5) Y6(-15.5,1.5) Y7(-14.5,1.5) Y8(-13.5,1.5) Y9(-12.5,1.5) Y10(-11.5,1.5) Y11(-10.5,1.5) Y12(-9.5,1.5) Y13(-8.5,1.5) Y14(-7.5,1.5) Y15(-6.5,1.5) Y16(-5.5,1.5) Y17(-4.5,1.5) Y18(-3.5,1.5) Y19(-2.5,1.5) Y20(-1.5,1.5) Y21(-0.5,1.5) Y22(0.5,1.5) Y23(1.5,1.5) Y24(2.5,1.5) Y25(3.5,1.5) Y26(4.5,1.5) Y27(5.5,1.5) Y28(6.5,1.5) Y29(7.5,1.5) Y30(8.5,1.5) Y31(9.5,1.5) Y32(10.5,1.5) Y33(11.5,1.5) Y34(12.5,1.5) Y35(13.5,1.5) Y36(14.5,1.5) Y37(15.5,1.5) Y38(16.5,1.5) Y39(17.5,1.5) Y40(18.5,1.5) Y41(19.5,1.5) Y42(20.5,1.5)
Top Overlay:
  circle w0.25: c-21.9,20.5 r0.125
  region: -20.669,21.25 -21.25,20.669 -21.25,21.25
  lines w0.2: -21.25,20.669 -20.669,21.25 ; -21.25,-21.25 21.25,-21.25 21.25,21.25 -21.25,21.25 -21.25,-21.25
Mechanical 13:
  lines w0.1: -21.25,-21.25 21.25,-21.25 21.25,21.25 -21.25,21.25 -21.25,-21.25
Mechanical 15:
  lines w0.1: -0.5,0 0.5,0 ; 0,-0.5 0,0.5 ; -22.25,-22.25 22.25,-22.25 22.25,22.25 -22.25,22.25 -22.25,-22.25
3D body: height 3.5, standoff 0, extent -21.25,-21.25 21.25,21.25

## FFG668 [mm] "668-Ball Flip Chip Fine Pitch Ball Grid Array (FFG668) - Pb-Free"
height 2.85
pads (668):
  round 0.5 smd: A2(-11.5,12.5) A3(-10.5,12.5) A4(-9.5,12.5) A5(-8.5,12.5) A6(-7.5,12.5) A7(-6.5,12.5) A8(-5.5,12.5) A9(-4.5,12.5) A10(-3.5,12.5) A11(-2.5,12.5) A12(-1.5,12.5) A13(-0.5,12.5) A14(0.5,12.5) A15(1.5,12.5) A16(2.5,12.5) A17(3.5,12.5) A18(4.5,12.5) A19(5.5,12.5) A20(6.5,12.5) A21(7.5,12.5) A22(8.5,12.5) A23(9.5,12.5) A24(10.5,12.5) A25(11.5,12.5) AA1(-12.5,-7.5) AA2(-11.5,-7.5) AA3(-10.5,-7.5) AA4(-9.5,-7.5) AA5(-8.5,-7.5) AA6(-7.5,-7.5) AA7(-6.5,-7.5) AA8(-5.5,-7.5) AA9(-4.5,-7.5) AA10(-3.5,-7.5) AA11(-2.5,-7.5) AA12(-1.5,-7.5) AA13(-0.5,-7.5) AA14(0.5,-7.5) AA15(1.5,-7.5) AA16(2.5,-7.5) AA17(3.5,-7.5) AA18(4.5,-7.5) AA19(5.5,-7.5) AA20(6.5,-7.5) AA21(7.5,-7.5) AA22(8.5,-7.5) AA23(9.5,-7.5) AA24(10.5,-7.5) AA25(11.5,-7.5) AA26(12.5,-7.5) AB1(-12.5,-8.5) AB2(-11.5,-8.5) AB3(-10.5,-8.5) AB4(-9.5,-8.5) AB5(-8.5,-8.5) AB6(-7.5,-8.5) AB7(-6.5,-8.5) AB8(-5.5,-8.5) AB9(-4.5,-8.5) AB10(-3.5,-8.5) AB11(-2.5,-8.5) AB12(-1.5,-8.5) AB13(-0.5,-8.5) AB14(0.5,-8.5) AB15(1.5,-8.5) AB16(2.5,-8.5) AB17(3.5,-8.5) AB18(4.5,-8.5) AB19(5.5,-8.5) AB20(6.5,-8.5) AB21(7.5,-8.5) AB22(8.5,-8.5) AB23(9.5,-8.5) AB24(10.5,-8.5) AB25(11.5,-8.5) AB26(12.5,-8.5) AC1(-12.5,-9.5) AC2(-11.5,-9.5) AC3(-10.5,-9.5) AC4(-9.5,-9.5) AC5(-8.5,-9.5) AC6(-7.5,-9.5) AC7(-6.5,-9.5) AC8(-5.5,-9.5) AC9(-4.5,-9.5) AC10(-3.5,-9.5) AC11(-2.5,-9.5) AC12(-1.5,-9.5) AC13(-0.5,-9.5) AC14(0.5,-9.5) AC15(1.5,-9.5) AC16(2.5,-9.5) AC17(3.5,-9.5) AC18(4.5,-9.5) AC19(5.5,-9.5) AC20(6.5,-9.5) AC21(7.5,-9.5) AC22(8.5,-9.5) AC23(9.5,-9.5) AC24(10.5,-9.5) AC25(11.5,-9.5) AC26(12.5,-9.5) AD1(-12.5,-10.5) AD2(-11.5,-10.5) AD3(-10.5,-10.5) AD4(-9.5,-10.5) AD5(-8.5,-10.5) AD6(-7.5,-10.5) AD7(-6.5,-10.5) AD8(-5.5,-10.5) AD9(-4.5,-10.5) AD10(-3.5,-10.5) AD11(-2.5,-10.5) AD12(-1.5,-10.5) AD13(-0.5,-10.5) AD14(0.5,-10.5) AD15(1.5,-10.5) AD16(2.5,-10.5) AD17(3.5,-10.5) AD18(4.5,-10.5) AD19(5.5,-10.5) AD20(6.5,-10.5) AD21(7.5,-10.5) AD22(8.5,-10.5) AD23(9.5,-10.5) AD24(10.5,-10.5) AD25(11.5,-10.5) AD26(12.5,-10.5) AE1(-12.5,-11.5) AE2(-11.5,-11.5) AE3(-10.5,-11.5) AE4(-9.5,-11.5) AE5(-8.5,-11.5) AE6(-7.5,-11.5) AE7(-6.5,-11.5) AE8(-5.5,-11.5) AE9(-4.5,-11.5) AE10(-3.5,-11.5) AE11(-2.5,-11.5) AE12(-1.5,-11.5) AE13(-0.5,-11.5) AE14(0.5,-11.5) AE15(1.5,-11.5) AE16(2.5,-11.5) AE17(3.5,-11.5) AE18(4.5,-11.5) AE19(5.5,-11.5) AE20(6.5,-11.5) AE21(7.5,-11.5) AE22(8.5,-11.5) AE23(9.5,-11.5) AE24(10.5,-11.5) AE25(11.5,-11.5) AE26(12.5,-11.5) AF2(-11.5,-12.5) AF3(-10.5,-12.5) AF4(-9.5,-12.5) AF5(-8.5,-12.5) AF6(-7.5,-12.5) AF7(-6.5,-12.5) AF8(-5.5,-12.5) AF9(-4.5,-12.5) AF10(-3.5,-12.5) AF11(-2.5,-12.5) AF12(-1.5,-12.5) AF13(-0.5,-12.5) AF14(0.5,-12.5) AF15(1.5,-12.5) AF16(2.5,-12.5) AF17(3.5,-12.5) AF18(4.5,-12.5) AF19(5.5,-12.5) AF20(6.5,-12.5) AF21(7.5,-12.5) AF22(8.5,-12.5) AF23(9.5,-12.5) AF24(10.5,-12.5) AF25(11.5,-12.5) B1(-12.5,11.5) B2(-11.5,11.5) B3(-10.5,11.5) B4(-9.5,11.5) B5(-8.5,11.5) B6(-7.5,11.5) B7(-6.5,11.5) B8(-5.5,11.5) B9(-4.5,11.5) B10(-3.5,11.5) B11(-2.5,11.5) B12(-1.5,11.5) B13(-0.5,11.5) B14(0.5,11.5) B15(1.5,11.5) B16(2.5,11.5) B17(3.5,11.5) B18(4.5,11.5) B19(5.5,11.5) B20(6.5,11.5) B21(7.5,11.5) B22(8.5,11.5) B23(9.5,11.5) B24(10.5,11.5) B25(11.5,11.5) B26(12.5,11.5) C1(-12.5,10.5) C2(-11.5,10.5) C3(-10.5,10.5) C4(-9.5,10.5) C5(-8.5,10.5) C6(-7.5,10.5) C7(-6.5,10.5) C8(-5.5,10.5) C9(-4.5,10.5) C10(-3.5,10.5) C11(-2.5,10.5) C12(-1.5,10.5) C13(-0.5,10.5) C14(0.5,10.5) C15(1.5,10.5) C16(2.5,10.5) C17(3.5,10.5) C18(4.5,10.5) C19(5.5,10.5) C20(6.5,10.5) C21(7.5,10.5) C22(8.5,10.5) C23(9.5,10.5) C24(10.5,10.5) C25(11.5,10.5) C26(12.5,10.5) D1(-12.5,9.5) D2(-11.5,9.5) D3(-10.5,9.5) D4(-9.5,9.5) D5(-8.5,9.5) D6(-7.5,9.5) D7(-6.5,9.5) D8(-5.5,9.5) D9(-4.5,9.5) D10(-3.5,9.5) D11(-2.5,9.5) D12(-1.5,9.5) D13(-0.5,9.5) D14(0.5,9.5) D15(1.5,9.5) D16(2.5,9.5) D17(3.5,9.5) D18(4.5,9.5) D19(5.5,9.5) D20(6.5,9.5) D21(7.5,9.5) D22(8.5,9.5) D23(9.5,9.5) D24(10.5,9.5) D25(11.5,9.5) D26(12.5,9.5) E1(-12.5,8.5) E2(-11.5,8.5) E3(-10.5,8.5) E4(-9.5,8.5) E5(-8.5,8.5) E6(-7.5,8.5) E7(-6.5,8.5) E8(-5.5,8.5) E9(-4.5,8.5) E10(-3.5,8.5) E11(-2.5,8.5) E12(-1.5,8.5) E13(-0.5,8.5) E14(0.5,8.5) E15(1.5,8.5) E16(2.5,8.5) E17(3.5,8.5) E18(4.5,8.5) E19(5.5,8.5) E20(6.5,8.5) E21(7.5,8.5) E22(8.5,8.5) E23(9.5,8.5) E24(10.5,8.5) E25(11.5,8.5) E26(12.5,8.5) F1(-12.5,7.5) F2(-11.5,7.5) F3(-10.5,7.5) F4(-9.5,7.5) F5(-8.5,7.5) F6(-7.5,7.5) F7(-6.5,7.5) F8(-5.5,7.5) F9(-4.5,7.5) F10(-3.5,7.5) F11(-2.5,7.5) F12(-1.5,7.5) F13(-0.5,7.5) F14(0.5,7.5) F15(1.5,7.5) F16(2.5,7.5) F17(3.5,7.5) F18(4.5,7.5) F19(5.5,7.5) F20(6.5,7.5) F21(7.5,7.5) F22(8.5,7.5) F23(9.5,7.5) F24(10.5,7.5) F25(11.5,7.5) F26(12.5,7.5) G1(-12.5,6.5) G2(-11.5,6.5) G3(-10.5,6.5) G4(-9.5,6.5) G5(-8.5,6.5) G6(-7.5,6.5) G7(-6.5,6.5) G8(-5.5,6.5) G9(-4.5,6.5) G10(-3.5,6.5) G11(-2.5,6.5) G12(-1.5,6.5) G13(-0.5,6.5) G14(0.5,6.5) G15(1.5,6.5) G16(2.5,6.5) G17(3.5,6.5) G18(4.5,6.5) G19(5.5,6.5) G20(6.5,6.5) G21(7.5,6.5) G22(8.5,6.5) G23(9.5,6.5) G24(10.5,6.5) G25(11.5,6.5) G26(12.5,6.5) H1(-12.5,5.5) H2(-11.5,5.5) H3(-10.5,5.5) H4(-9.5,5.5) H5(-8.5,5.5) H6(-7.5,5.5) H7(-6.5,5.5) H8(-5.5,5.5) H9(-4.5,5.5) H10(-3.5,5.5) H11(-2.5,5.5) H12(-1.5,5.5) H13(-0.5,5.5) H14(0.5,5.5) H15(1.5,5.5) H16(2.5,5.5) H17(3.5,5.5) H18(4.5,5.5) H19(5.5,5.5) H20(6.5,5.5) H21(7.5,5.5) H22(8.5,5.5) H23(9.5,5.5) H24(10.5,5.5) H25(11.5,5.5) H26(12.5,5.5) J1(-12.5,4.5) J2(-11.5,4.5) J3(-10.5,4.5) J4(-9.5,4.5) J5(-8.5,4.5) J6(-7.5,4.5) J7(-6.5,4.5) J8(-5.5,4.5) J10(-3.5,4.5) J11(-2.5,4.5) J12(-1.5,4.5) J13(-0.5,4.5) J14(0.5,4.5) J15(1.5,4.5) J16(2.5,4.5) J17(3.5,4.5) J19(5.5,4.5) J20(6.5,4.5) J21(7.5,4.5) J22(8.5,4.5) J23(9.5,4.5) J24(10.5,4.5) J25(11.5,4.5) J26(12.5,4.5) K1(-12.5,3.5) K2(-11.5,3.5) K3(-10.5,3.5) K4(-9.5,3.5) K5(-8.5,3.5) K6(-7.5,3.5) K7(-6.5,3.5) K8(-5.5,3.5) K9(-4.5,3.5) K10(-3.5,3.5) K11(-2.5,3.5) K12(-1.5,3.5) K13(-0.5,3.5) K14(0.5,3.5) K15(1.5,3.5) K16(2.5,3.5) K17(3.5,3.5) K18(4.5,3.5) K19(5.5,3.5) K20(6.5,3.5) K21(7.5,3.5) K22(8.5,3.5) K23(9.5,3.5) K24(10.5,3.5) K25(11.5,3.5) K26(12.5,3.5) L1(-12.5,2.5) L2(-11.5,2.5) L3(-10.5,2.5) L4(-9.5,2.5) L5(-8.5,2.5) L6(-7.5,2.5) L7(-6.5,2.5) L8(-5.5,2.5) L9(-4.5,2.5) L10(-3.5,2.5) L11(-2.5,2.5) L12(-1.5,2.5) L13(-0.5,2.5) L14(0.5,2.5) L15(1.5,2.5) L16(2.5,2.5) L17(3.5,2.5) L18(4.5,2.5) L19(5.5,2.5) L20(6.5,2.5) L21(7.5,2.5) L22(8.5,2.5) L23(9.5,2.5) L24(10.5,2.5) L25(11.5,2.5) L26(12.5,2.5) M1(-12.5,1.5) M2(-11.5,1.5) M3(-10.5,1.5) M4(-9.5,1.5) M5(-8.5,1.5) M6(-7.5,1.5) M7(-6.5,1.5) M8(-5.5,1.5) M9(-4.5,1.5) M10(-3.5,1.5) M11(-2.5,1.5) M12(-1.5,1.5) M13(-0.5,1.5) M14(0.5,1.5) M15(1.5,1.5) M16(2.5,1.5) M17(3.5,1.5) M18(4.5,1.5) M19(5.5,1.5) M20(6.5,1.5) M21(7.5,1.5) M22(8.5,1.5) M23(9.5,1.5) M24(10.5,1.5) M25(11.5,1.5) M26(12.5,1.5) N1(-12.5,0.5) N2(-11.5,0.5) N3(-10.5,0.5) N4(-9.5,0.5) N5(-8.5,0.5) N6(-7.5,0.5) N7(-6.5,0.5) N8(-5.5,0.5) N9(-4.5,0.5) N10(-3.5,0.5) N11(-2.5,0.5) N12(-1.5,0.5) N13(-0.5,0.5) N14(0.5,0.5) N15(1.5,0.5) N16(2.5,0.5) N17(3.5,0.5) N18(4.5,0.5) N19(5.5,0.5) N20(6.5,0.5) N21(7.5,0.5) N22(8.5,0.5) N23(9.5,0.5) N24(10.5,0.5) N25(11.5,0.5) N26(12.5,0.5) P1(-12.5,-0.5) P2(-11.5,-0.5) P3(-10.5,-0.5) P4(-9.5,-0.5) P5(-8.5,-0.5) P6(-7.5,-0.5) P7(-6.5,-0.5) P8(-5.5,-0.5) P9(-4.5,-0.5) P10(-3.5,-0.5) P11(-2.5,-0.5) P12(-1.5,-0.5) P13(-0.5,-0.5) P14(0.5,-0.5) P15(1.5,-0.5) P16(2.5,-0.5) P17(3.5,-0.5) P18(4.5,-0.5) P19(5.5,-0.5) P20(6.5,-0.5) P21(7.5,-0.5) P22(8.5,-0.5) P23(9.5,-0.5) P24(10.5,-0.5) P25(11.5,-0.5) P26(12.5,-0.5) R1(-12.5,-1.5) R2(-11.5,-1.5) R3(-10.5,-1.5) R4(-9.5,-1.5) R5(-8.5,-1.5) R6(-7.5,-1.5) R7(-6.5,-1.5) R8(-5.5,-1.5) R9(-4.5,-1.5) R10(-3.5,-1.5) R11(-2.5,-1.5) R12(-1.5,-1.5) R13(-0.5,-1.5) R14(0.5,-1.5) R15(1.5,-1.5) R16(2.5,-1.5) R17(3.5,-1.5) R18(4.5,-1.5) R19(5.5,-1.5) R20(6.5,-1.5) R21(7.5,-1.5) R22(8.5,-1.5) R23(9.5,-1.5) R24(10.5,-1.5) R25(11.5,-1.5) R26(12.5,-1.5) T1(-12.5,-2.5) T2(-11.5,-2.5) T3(-10.5,-2.5) T4(-9.5,-2.5) T5(-8.5,-2.5) T6(-7.5,-2.5) T7(-6.5,-2.5) T8(-5.5,-2.5) T9(-4.5,-2.5) T10(-3.5,-2.5) T11(-2.5,-2.5) T12(-1.5,-2.5) T13(-0.5,-2.5) T14(0.5,-2.5) T15(1.5,-2.5) T16(2.5,-2.5) T17(3.5,-2.5) T18(4.5,-2.5) T19(5.5,-2.5) T20(6.5,-2.5) T21(7.5,-2.5) T22(8.5,-2.5) T23(9.5,-2.5) T24(10.5,-2.5) T25(11.5,-2.5) T26(12.5,-2.5) U1(-12.5,-3.5) U2(-11.5,-3.5) U3(-10.5,-3.5) U4(-9.5,-3.5) U5(-8.5,-3.5) U6(-7.5,-3.5) U7(-6.5,-3.5) U8(-5.5,-3.5) U9(-4.5,-3.5) U10(-3.5,-3.5) U11(-2.5,-3.5) U12(-1.5,-3.5) U13(-0.5,-3.5) U14(0.5,-3.5) U15(1.5,-3.5) U16(2.5,-3.5) U17(3.5,-3.5) U18(4.5,-3.5) U19(5.5,-3.5) U20(6.5,-3.5) U21(7.5,-3.5) U22(8.5,-3.5) U23(9.5,-3.5) U24(10.5,-3.5) U25(11.5,-3.5) U26(12.5,-3.5) V1(-12.5,-4.5) V2(-11.5,-4.5) V3(-10.5,-4.5) V4(-9.5,-4.5) V5(-8.5,-4.5) V6(-7.5,-4.5) V7(-6.5,-4.5) V8(-5.5,-4.5) V10(-3.5,-4.5) V11(-2.5,-4.5) V12(-1.5,-4.5) V13(-0.5,-4.5) V14(0.5,-4.5) V15(1.5,-4.5) V16(2.5,-4.5) V17(3.5,-4.5) V19(5.5,-4.5) V20(6.5,-4.5) V21(7.5,-4.5) V22(8.5,-4.5) V23(9.5,-4.5) V24(10.5,-4.5) V25(11.5,-4.5) V26(12.5,-4.5) W1(-12.5,-5.5) W2(-11.5,-5.5) W3(-10.5,-5.5) W4(-9.5,-5.5) W5(-8.5,-5.5) W6(-7.5,-5.5) W7(-6.5,-5.5) W8(-5.5,-5.5) W9(-4.5,-5.5) W10(-3.5,-5.5) W11(-2.5,-5.5) W12(-1.5,-5.5) W13(-0.5,-5.5) W14(0.5,-5.5) W15(1.5,-5.5) W16(2.5,-5.5) W17(3.5,-5.5) W18(4.5,-5.5) W19(5.5,-5.5) W20(6.5,-5.5) W21(7.5,-5.5) W22(8.5,-5.5) W23(9.5,-5.5) W24(10.5,-5.5) W25(11.5,-5.5) W26(12.5,-5.5) Y1(-12.5,-6.5) Y2(-11.5,-6.5) Y3(-10.5,-6.5) Y4(-9.5,-6.5) Y5(-8.5,-6.5) Y6(-7.5,-6.5) Y7(-6.5,-6.5) Y8(-5.5,-6.5) Y9(-4.5,-6.5) Y10(-3.5,-6.5) Y11(-2.5,-6.5) Y12(-1.5,-6.5) Y13(-0.5,-6.5) Y14(0.5,-6.5) Y15(1.5,-6.5) Y16(2.5,-6.5) Y17(3.5,-6.5) Y18(4.5,-6.5) Y19(5.5,-6.5) Y20(6.5,-6.5) Y21(7.5,-6.5) Y22(8.5,-6.5) Y23(9.5,-6.5) Y24(10.5,-6.5) Y25(11.5,-6.5) Y26(12.5,-6.5)
Top Overlay:
  circle w0.25: c-14.15,12.5 r0.125
  region: -12.5,13.5 -13.5,12.5 -13.5,13.5
  lines w0.2: -13.5,12.5 -12.5,13.5 ; -13.5,-13.5 -13.5,13.5 13.5,13.5 13.5,-13.5 -13.5,-13.5
Mechanical 13:
  lines w0.1: -13.5,-13.5 -13.5,13.5 13.5,13.5 13.5,-13.5 -13.5,-13.5
Mechanical 15:
  lines w0.1: -0.5,0 0.5,0 ; 0,-0.5 0,0.5 ; -14.5,-14.5 -14.5,14.5 14.5,14.5 14.5,-14.5 -14.5,-14.5
3D body: height 2.85, standoff 0, extent -13.5,-13.5 13.5,13.5

## FFG672 [mm] "672-Ball Flip Chip Fine Pitch Ball Grid Array (FFG672) - Pb-Free"
height 3
pads (672):
  round 0.5 smd: A2(-11.5,12.5) A3(-10.5,12.5) A4(-9.5,12.5) A5(-8.5,12.5) A6(-7.5,12.5) A7(-6.5,12.5) A8(-5.5,12.5) A9(-4.5,12.5) A10(-3.5,12.5) A11(-2.5,12.5) A12(-1.5,12.5) A13(-0.5,12.5) A14(0.5,12.5) A15(1.5,12.5) A16(2.5,12.5) A17(3.5,12.5) A18(4.5,12.5) A19(5.5,12.5) A20(6.5,12.5) A21(7.5,12.5) A22(8.5,12.5) A23(9.5,12.5) A24(10.5,12.5) A25(11.5,12.5) AA1(-12.5,-7.5) AA2(-11.5,-7.5) AA3(-10.5,-7.5) AA4(-9.5,-7.5) AA5(-8.5,-7.5) AA6(-7.5,-7.5) AA7(-6.5,-7.5) AA8(-5.5,-7.5) AA9(-4.5,-7.5) AA10(-3.5,-7.5) AA11(-2.5,-7.5) AA12(-1.5,-7.5) AA13(-0.5,-7.5) AA14(0.5,-7.5) AA15(1.5,-7.5) AA16(2.5,-7.5) AA17(3.5,-7.5) AA18(4.5,-7.5) AA19(5.5,-7.5) AA20(6.5,-7.5) AA21(7.5,-7.5) AA22(8.5,-7.5) AA23(9.5,-7.5) AA24(10.5,-7.5) AA25(11.5,-7.5) AA26(12.5,-7.5) AB1(-12.5,-8.5) AB2(-11.5,-8.5) AB3(-10.5,-8.5) AB4(-9.5,-8.5) AB5(-8.5,-8.5) AB6(-7.5,-8.5) AB7(-6.5,-8.5) AB8(-5.5,-8.5) AB9(-4.5,-8.5) AB10(-3.5,-8.5) AB11(-2.5,-8.5) AB12(-1.5,-8.5) AB13(-0.5,-8.5) AB14(0.5,-8.5) AB15(1.5,-8.5) AB16(2.5,-8.5) AB17(3.5,-8.5) AB18(4.5,-8.5) AB19(5.5,-8.5) AB20(6.5,-8.5) AB21(7.5,-8.5) AB22(8.5,-8.5) AB23(9.5,-8.5) AB24(10.5,-8.5) AB25(11.5,-8.5) AB26(12.5,-8.5) AC1(-12.5,-9.5) AC2(-11.5,-9.5) AC3(-10.5,-9.5) AC4(-9.5,-9.5) AC5(-8.5,-9.5) AC6(-7.5,-9.5) AC7(-6.5,-9.5) AC8(-5.5,-9.5) AC9(-4.5,-9.5) AC10(-3.5,-9.5) AC11(-2.5,-9.5) AC12(-1.5,-9.5) AC13(-0.5,-9.5) AC14(0.5,-9.5) AC15(1.5,-9.5) AC16(2.5,-9.5) AC17(3.5,-9.5) AC18(4.5,-9.5) AC19(5.5,-9.5) AC20(6.5,-9.5) AC21(7.5,-9.5) AC22(8.5,-9.5) AC23(9.5,-9.5) AC24(10.5,-9.5) AC25(11.5,-9.5) AC26(12.5,-9.5) AD1(-12.5,-10.5) AD2(-11.5,-10.5) AD3(-10.5,-10.5) AD4(-9.5,-10.5) AD5(-8.5,-10.5) AD6(-7.5,-10.5) AD7(-6.5,-10.5) AD8(-5.5,-10.5) AD9(-4.5,-10.5) AD10(-3.5,-10.5) AD11(-2.5,-10.5) AD12(-1.5,-10.5) AD13(-0.5,-10.5) AD14(0.5,-10.5) AD15(1.5,-10.5) AD16(2.5,-10.5) AD17(3.5,-10.5) AD18(4.5,-10.5) AD19(5.5,-10.5) AD20(6.5,-10.5) AD21(7.5,-10.5) AD22(8.5,-10.5) AD23(9.5,-10.5) AD24(10.5,-10.5) AD25(11.5,-10.5) AD26(12.5,-10.5) AE1(-12.5,-11.5) AE2(-11.5,-11.5) AE3(-10.5,-11.5) AE4(-9.5,-11.5) AE5(-8.5,-11.5) AE6(-7.5,-11.5) AE7(-6.5,-11.5) AE8(-5.5,-11.5) AE9(-4.5,-11.5) AE10(-3.5,-11.5) AE11(-2.5,-11.5) AE12(-1.5,-11.5) AE13(-0.5,-11.5) AE14(0.5,-11.5) AE15(1.5,-11.5) AE16(2.5,-11.5) AE17(3.5,-11.5) AE18(4.5,-11.5) AE19(5.5,-11.5) AE20(6.5,-11.5) AE21(7.5,-11.5) AE22(8.5,-11.5) AE23(9.5,-11.5) AE24(10.5,-11.5) AE25(11.5,-11.5) AE26(12.5,-11.5) AF2(-11.5,-12.5) AF3(-10.5,-12.5) AF4(-9.5,-12.5) AF5(-8.5,-12.5) AF6(-7.5,-12.5) AF7(-6.5,-12.5) AF8(-5.5,-12.5) AF9(-4.5,-12.5) AF10(-3.5,-12.5) AF11(-2.5,-12.5) AF12(-1.5,-12.5) AF13(-0.5,-12.5) AF14(0.5,-12.5) AF15(1.5,-12.5) AF16(2.5,-12.5) AF17(3.5,-12.5) AF18(4.5,-12.5) AF19(5.5,-12.5) AF20(6.5,-12.5) AF21(7.5,-12.5) AF22(8.5,-12.5) AF23(9.5,-12.5) AF24(10.5,-12.5) AF25(11.5,-12.5) B1(-12.5,11.5) B2(-11.5,11.5) B3(-10.5,11.5) B4(-9.5,11.5) B5(-8.5,11.5) B6(-7.5,11.5) B7(-6.5,11.5) B8(-5.5,11.5) B9(-4.5,11.5) B10(-3.5,11.5) B11(-2.5,11.5) B12(-1.5,11.5) B13(-0.5,11.5) B14(0.5,11.5) B15(1.5,11.5) B16(2.5,11.5) B17(3.5,11.5) B18(4.5,11.5) B19(5.5,11.5) B20(6.5,11.5) B21(7.5,11.5) B22(8.5,11.5) B23(9.5,11.5) B24(10.5,11.5) B25(11.5,11.5) B26(12.5,11.5) C1(-12.5,10.5) C2(-11.5,10.5) C3(-10.5,10.5) C4(-9.5,10.5) C5(-8.5,10.5) C6(-7.5,10.5) C7(-6.5,10.5) C8(-5.5,10.5) C9(-4.5,10.5) C10(-3.5,10.5) C11(-2.5,10.5) C12(-1.5,10.5) C13(-0.5,10.5) C14(0.5,10.5) C15(1.5,10.5) C16(2.5,10.5) C17(3.5,10.5) C18(4.5,10.5) C19(5.5,10.5) C20(6.5,10.5) C21(7.5,10.5) C22(8.5,10.5) C23(9.5,10.5) C24(10.5,10.5) C25(11.5,10.5) C26(12.5,10.5) D1(-12.5,9.5) D2(-11.5,9.5) D3(-10.5,9.5) D4(-9.5,9.5) D5(-8.5,9.5) D6(-7.5,9.5) D7(-6.5,9.5) D8(-5.5,9.5) D9(-4.5,9.5) D10(-3.5,9.5) D11(-2.5,9.5) D12(-1.5,9.5) D13(-0.5,9.5) D14(0.5,9.5) D15(1.5,9.5) D16(2.5,9.5) D17(3.5,9.5) D18(4.5,9.5) D19(5.5,9.5) D20(6.5,9.5) D21(7.5,9.5) D22(8.5,9.5) D23(9.5,9.5) D24(10.5,9.5) D25(11.5,9.5) D26(12.5,9.5) E1(-12.5,8.5) E2(-11.5,8.5) E3(-10.5,8.5) E4(-9.5,8.5) E5(-8.5,8.5) E6(-7.5,8.5) E7(-6.5,8.5) E8(-5.5,8.5) E9(-4.5,8.5) E10(-3.5,8.5) E11(-2.5,8.5) E12(-1.5,8.5) E13(-0.5,8.5) E14(0.5,8.5) E15(1.5,8.5) E16(2.5,8.5) E17(3.5,8.5) E18(4.5,8.5) E19(5.5,8.5) E20(6.5,8.5) E21(7.5,8.5) E22(8.5,8.5) E23(9.5,8.5) E24(10.5,8.5) E25(11.5,8.5) E26(12.5,8.5) F1(-12.5,7.5) F2(-11.5,7.5) F3(-10.5,7.5) F4(-9.5,7.5) F5(-8.5,7.5) F6(-7.5,7.5) F7(-6.5,7.5) F8(-5.5,7.5) F9(-4.5,7.5) F10(-3.5,7.5) F11(-2.5,7.5) F12(-1.5,7.5) F13(-0.5,7.5) F14(0.5,7.5) F15(1.5,7.5) F16(2.5,7.5) F17(3.5,7.5) F18(4.5,7.5) F19(5.5,7.5) F20(6.5,7.5) F21(7.5,7.5) F22(8.5,7.5) F23(9.5,7.5) F24(10.5,7.5) F25(11.5,7.5) F26(12.5,7.5) G1(-12.5,6.5) G2(-11.5,6.5) G3(-10.5,6.5) G4(-9.5,6.5) G5(-8.5,6.5) G6(-7.5,6.5) G7(-6.5,6.5) G8(-5.5,6.5) G9(-4.5,6.5) G10(-3.5,6.5) G11(-2.5,6.5) G12(-1.5,6.5) G13(-0.5,6.5) G14(0.5,6.5) G15(1.5,6.5) G16(2.5,6.5) G17(3.5,6.5) G18(4.5,6.5) G19(5.5,6.5) G20(6.5,6.5) G21(7.5,6.5) G22(8.5,6.5) G23(9.5,6.5) G24(10.5,6.5) G25(11.5,6.5) G26(12.5,6.5) H1(-12.5,5.5) H2(-11.5,5.5) H3(-10.5,5.5) H4(-9.5,5.5) H5(-8.5,5.5) H6(-7.5,5.5) H7(-6.5,5.5) H8(-5.5,5.5) H9(-4.5,5.5) H10(-3.5,5.5) H11(-2.5,5.5) H12(-1.5,5.5) H13(-0.5,5.5) H14(0.5,5.5) H15(1.5,5.5) H16(2.5,5.5) H17(3.5,5.5) H18(4.5,5.5) H19(5.5,5.5) H20(6.5,5.5) H21(7.5,5.5) H22(8.5,5.5) H23(9.5,5.5) H24(10.5,5.5) H25(11.5,5.5) H26(12.5,5.5) J1(-12.5,4.5) J2(-11.5,4.5) J3(-10.5,4.5) J4(-9.5,4.5) J5(-8.5,4.5) J6(-7.5,4.5) J7(-6.5,4.5) J8(-5.5,4.5) J9(-4.5,4.5) J10(-3.5,4.5) J11(-2.5,4.5) J12(-1.5,4.5) J13(-0.5,4.5) J14(0.5,4.5) J15(1.5,4.5) J16(2.5,4.5) J17(3.5,4.5) J18(4.5,4.5) J19(5.5,4.5) J20(6.5,4.5) J21(7.5,4.5) J22(8.5,4.5) J23(9.5,4.5) J24(10.5,4.5) J25(11.5,4.5) J26(12.5,4.5) K1(-12.5,3.5) K2(-11.5,3.5) K3(-10.5,3.5) K4(-9.5,3.5) K5(-8.5,3.5) K6(-7.5,3.5) K7(-6.5,3.5) K8(-5.5,3.5) K9(-4.5,3.5) K10(-3.5,3.5) K11(-2.5,3.5) K12(-1.5,3.5) K13(-0.5,3.5) K14(0.5,3.5) K15(1.5,3.5) K16(2.5,3.5) K17(3.5,3.5) K18(4.5,3.5) K19(5.5,3.5) K20(6.5,3.5) K21(7.5,3.5) K22(8.5,3.5) K23(9.5,3.5) K24(10.5,3.5) K25(11.5,3.5) K26(12.5,3.5) L1(-12.5,2.5) L2(-11.5,2.5) L3(-10.5,2.5) L4(-9.5,2.5) L5(-8.5,2.5) L6(-7.5,2.5) L7(-6.5,2.5) L8(-5.5,2.5) L9(-4.5,2.5) L10(-3.5,2.5) L11(-2.5,2.5) L12(-1.5,2.5) L13(-0.5,2.5) L14(0.5,2.5) L15(1.5,2.5) L16(2.5,2.5) L17(3.5,2.5) L18(4.5,2.5) L19(5.5,2.5) L20(6.5,2.5) L21(7.5,2.5) L22(8.5,2.5) L23(9.5,2.5) L24(10.5,2.5) L25(11.5,2.5) L26(12.5,2.5) M1(-12.5,1.5) M2(-11.5,1.5) M3(-10.5,1.5) M4(-9.5,1.5) M5(-8.5,1.5) M6(-7.5,1.5) M7(-6.5,1.5) M8(-5.5,1.5) M9(-4.5,1.5) M10(-3.5,1.5) M11(-2.5,1.5) M12(-1.5,1.5) M13(-0.5,1.5) M14(0.5,1.5) M15(1.5,1.5) M16(2.5,1.5) M17(3.5,1.5) M18(4.5,1.5) M19(5.5,1.5) M20(6.5,1.5) M21(7.5,1.5) M22(8.5,1.5) M23(9.5,1.5) M24(10.5,1.5) M25(11.5,1.5) M26(12.5,1.5) N1(-12.5,0.5) N2(-11.5,0.5) N3(-10.5,0.5) N4(-9.5,0.5) N5(-8.5,0.5) N6(-7.5,0.5) N7(-6.5,0.5) N8(-5.5,0.5) N9(-4.5,0.5) N10(-3.5,0.5) N11(-2.5,0.5) N12(-1.5,0.5) N13(-0.5,0.5) N14(0.5,0.5) N15(1.5,0.5) N16(2.5,0.5) N17(3.5,0.5) N18(4.5,0.5) N19(5.5,0.5) N20(6.5,0.5) N21(7.5,0.5) N22(8.5,0.5) N23(9.5,0.5) N24(10.5,0.5) N25(11.5,0.5) N26(12.5,0.5) P1(-12.5,-0.5) P2(-11.5,-0.5) P3(-10.5,-0.5) P4(-9.5,-0.5) P5(-8.5,-0.5) P6(-7.5,-0.5) P7(-6.5,-0.5) P8(-5.5,-0.5) P9(-4.5,-0.5) P10(-3.5,-0.5) P11(-2.5,-0.5) P12(-1.5,-0.5) P13(-0.5,-0.5) P14(0.5,-0.5) P15(1.5,-0.5) P16(2.5,-0.5) P17(3.5,-0.5) P18(4.5,-0.5) P19(5.5,-0.5) P20(6.5,-0.5) P21(7.5,-0.5) P22(8.5,-0.5) P23(9.5,-0.5) P24(10.5,-0.5) P25(11.5,-0.5) P26(12.5,-0.5) R1(-12.5,-1.5) R2(-11.5,-1.5) R3(-10.5,-1.5) R4(-9.5,-1.5) R5(-8.5,-1.5) R6(-7.5,-1.5) R7(-6.5,-1.5) R8(-5.5,-1.5) R9(-4.5,-1.5) R10(-3.5,-1.5) R11(-2.5,-1.5) R12(-1.5,-1.5) R13(-0.5,-1.5) R14(0.5,-1.5) R15(1.5,-1.5) R16(2.5,-1.5) R17(3.5,-1.5) R18(4.5,-1.5) R19(5.5,-1.5) R20(6.5,-1.5) R21(7.5,-1.5) R22(8.5,-1.5) R23(9.5,-1.5) R24(10.5,-1.5) R25(11.5,-1.5) R26(12.5,-1.5) T1(-12.5,-2.5) T2(-11.5,-2.5) T3(-10.5,-2.5) T4(-9.5,-2.5) T5(-8.5,-2.5) T6(-7.5,-2.5) T7(-6.5,-2.5) T8(-5.5,-2.5) T9(-4.5,-2.5) T10(-3.5,-2.5) T11(-2.5,-2.5) T12(-1.5,-2.5) T13(-0.5,-2.5) T14(0.5,-2.5) T15(1.5,-2.5) T16(2.5,-2.5) T17(3.5,-2.5) T18(4.5,-2.5) T19(5.5,-2.5) T20(6.5,-2.5) T21(7.5,-2.5) T22(8.5,-2.5) T23(9.5,-2.5) T24(10.5,-2.5) T25(11.5,-2.5) T26(12.5,-2.5) U1(-12.5,-3.5) U2(-11.5,-3.5) U3(-10.5,-3.5) U4(-9.5,-3.5) U5(-8.5,-3.5) U6(-7.5,-3.5) U7(-6.5,-3.5) U8(-5.5,-3.5) U9(-4.5,-3.5) U10(-3.5,-3.5) U11(-2.5,-3.5) U12(-1.5,-3.5) U13(-0.5,-3.5) U14(0.5,-3.5) U15(1.5,-3.5) U16(2.5,-3.5) U17(3.5,-3.5) U18(4.5,-3.5) U19(5.5,-3.5) U20(6.5,-3.5) U21(7.5,-3.5) U22(8.5,-3.5) U23(9.5,-3.5) U24(10.5,-3.5) U25(11.5,-3.5) U26(12.5,-3.5) V1(-12.5,-4.5) V2(-11.5,-4.5) V3(-10.5,-4.5) V4(-9.5,-4.5) V5(-8.5,-4.5) V6(-7.5,-4.5) V7(-6.5,-4.5) V8(-5.5,-4.5) V9(-4.5,-4.5) V10(-3.5,-4.5) V11(-2.5,-4.5) V12(-1.5,-4.5) V13(-0.5,-4.5) V14(0.5,-4.5) V15(1.5,-4.5) V16(2.5,-4.5) V17(3.5,-4.5) V18(4.5,-4.5) V19(5.5,-4.5) V20(6.5,-4.5) V21(7.5,-4.5) V22(8.5,-4.5) V23(9.5,-4.5) V24(10.5,-4.5) V25(11.5,-4.5) V26(12.5,-4.5) W1(-12.5,-5.5) W2(-11.5,-5.5) W3(-10.5,-5.5) W4(-9.5,-5.5) W5(-8.5,-5.5) W6(-7.5,-5.5) W7(-6.5,-5.5) W8(-5.5,-5.5) W9(-4.5,-5.5) W10(-3.5,-5.5) W11(-2.5,-5.5) W12(-1.5,-5.5) W13(-0.5,-5.5) W14(0.5,-5.5) W15(1.5,-5.5) W16(2.5,-5.5) W17(3.5,-5.5) W18(4.5,-5.5) W19(5.5,-5.5) W20(6.5,-5.5) W21(7.5,-5.5) W22(8.5,-5.5) W23(9.5,-5.5) W24(10.5,-5.5) W25(11.5,-5.5) W26(12.5,-5.5) Y1(-12.5,-6.5) Y2(-11.5,-6.5) Y3(-10.5,-6.5) Y4(-9.5,-6.5) Y5(-8.5,-6.5) Y6(-7.5,-6.5) Y7(-6.5,-6.5) Y8(-5.5,-6.5) Y9(-4.5,-6.5) Y10(-3.5,-6.5) Y11(-2.5,-6.5) Y12(-1.5,-6.5) Y13(-0.5,-6.5) Y14(0.5,-6.5) Y15(1.5,-6.5) Y16(2.5,-6.5) Y17(3.5,-6.5) Y18(4.5,-6.5) Y19(5.5,-6.5) Y20(6.5,-6.5) Y21(7.5,-6.5) Y22(8.5,-6.5) Y23(9.5,-6.5) Y24(10.5,-6.5) Y25(11.5,-6.5) Y26(12.5,-6.5)
Top Overlay:
  circle w0.25: c-14.15,12.5 r0.125
  region: -12.5,13.5 -13.5,12.5 -13.5,13.5
  lines w0.2: -13.5,12.5 -12.5,13.5 ; -13.5,-13.5 13.5,-13.5 13.5,13.5 -13.5,13.5 -13.5,-13.5
Mechanical 13:
  lines w0.1: -13.5,-13.5 13.5,-13.5 13.5,13.5 -13.5,13.5 -13.5,-13.5
Mechanical 15:
  lines w0.1: -0.5,0 0.5,0 ; 0,-0.5 0,0.5 ; -14.5,-14.5 14.5,-14.5 14.5,14.5 -14.5,14.5 -14.5,-14.5
3D body: height 3, standoff 0, extent -13.5,-13.5 13.5,13.5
